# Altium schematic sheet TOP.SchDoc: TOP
size A4; SheetNumber: 1; SheetTotal: 1
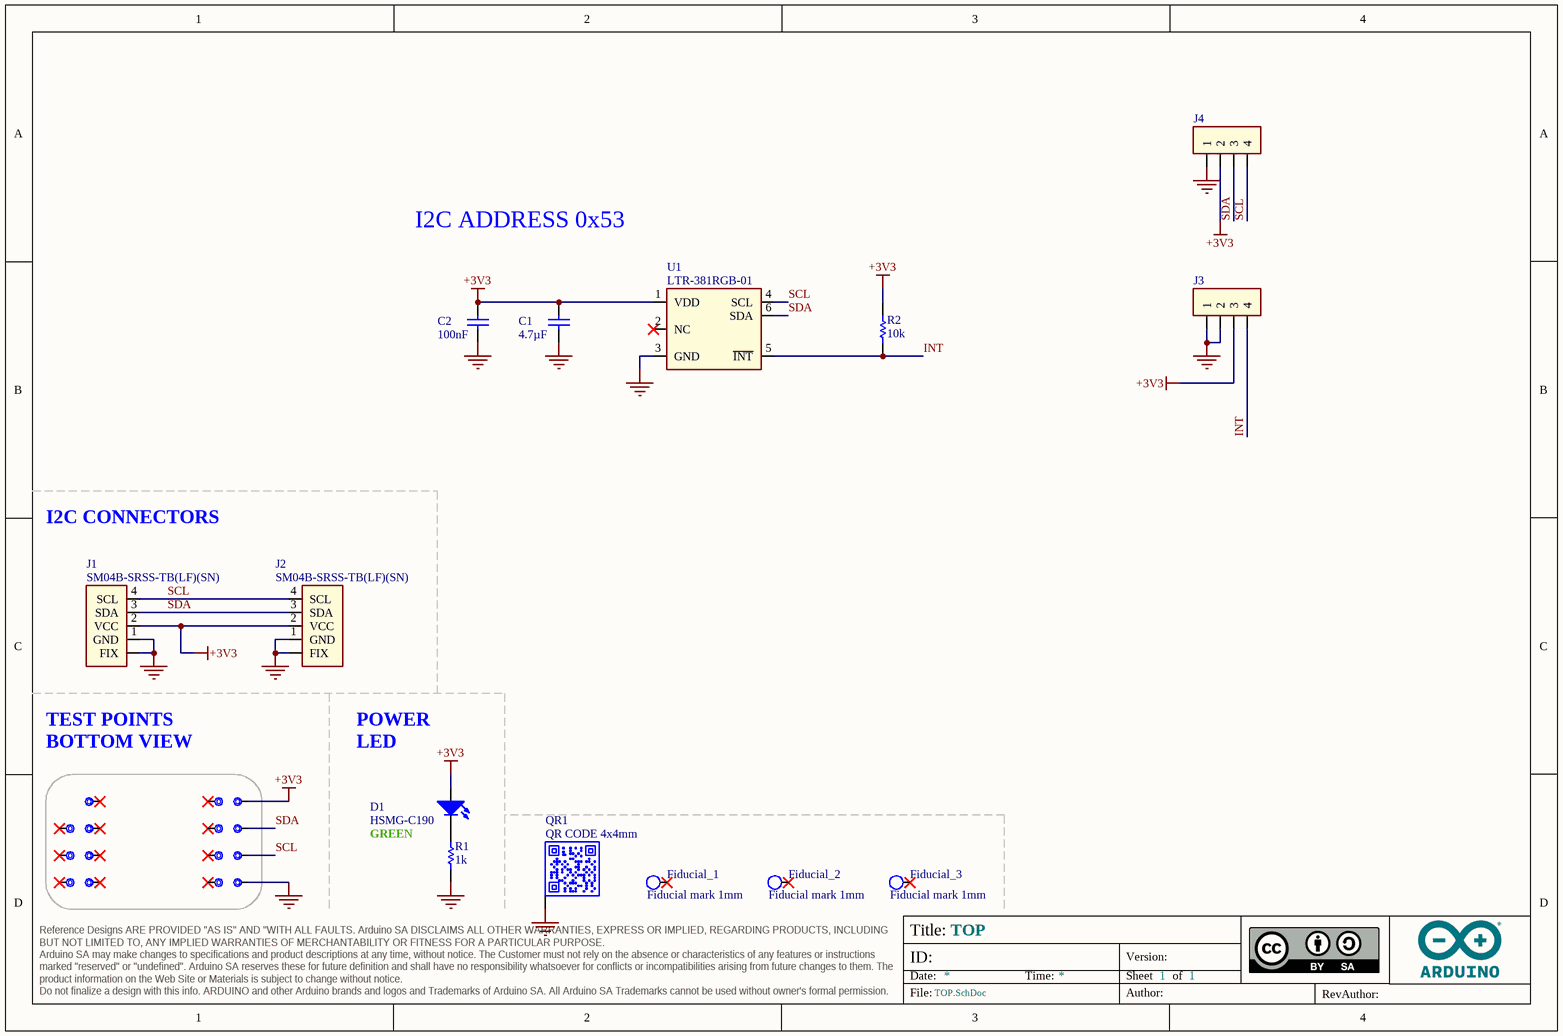
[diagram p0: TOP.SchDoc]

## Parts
3V3  Test point 1.00mm  [TP-1.00MM]  (value not drawn)  (no BOM)
C1  value 4.7µF  [CAP-0603]  (hidden comment: GRM188R61C475KAAJD)
C2  value 100nF  [CAP-0402]  (hidden comment: 0402B104K160CT)
D1  HSMG-C190  [LEDC1608X80N-AK]
Fiducial_1  Fiducial mark 1mm  [Fiducial mark 1mm-Footprint-1]  (no BOM)
Fiducial_2  Fiducial mark 1mm  [Fiducial mark 1mm-Footprint-1]  (no BOM)
Fiducial_3  Fiducial mark 1mm  [Fiducial mark 1mm-Footprint-1]  (no BOM)
GND  Test point 1.00mm  [TP-1.00MM]  (value not drawn)  (no BOM)
J1  SM04B-SRSS-TB(LF)(SN)  [SM04B-SRSS-TB(LF)(SN)-Footprint-1]
J2  SM04B-SRSS-TB(LF)(SN)  [SM04B-SRSS-TB(LF)(SN)-Footprint-1]
J3  HEADER TH 2.54mm VERT. 1x004POS  [PIN HEADER 2.54mm VERT. 1x4POS-Footprint-1]  (value not drawn)  (no BOM)
J4  HEADER TH 2.54mm VERT. 1x004POS  [PIN HEADER 2.54mm VERT. 1x4POS-Footprint-1]  (value not drawn)  (no BOM)
NRST  Test point 1.00mm  [TP-1.00MM]  (value not drawn)  (no BOM)
PA6  Test point 1.00mm  [TP-1.00MM]  (value not drawn)  (no BOM)
PA7  Test point 1.00mm  [TP-1.00MM]  (value not drawn)  (no BOM)
PC14  Test point 1.00mm  [TP-1.00MM]  (value not drawn)  (no BOM)
PC15  Test point 1.00mm  [TP-1.00MM]  (value not drawn)  (no BOM)
QR1  QR CODE 4x4mm  [QR CODE 4x4mm]  (no BOM)
R1  value 1k  [RES-0402]  (hidden comment: CRCW04021K00FKEDC)
R2  value 10k  [RES-0402]  (hidden comment: CRCW040210K0FKED)
SCL  Test point 1.00mm  [TP-1.00MM]  (value not drawn)  (no BOM)
SDA  Test point 1.00mm  [TP-1.00MM]  (value not drawn)  (no BOM)
SWCLK  Test point 1.00mm  [TP-1.00MM]  (value not drawn)  (no BOM)
SWDIO  Test point 1.00mm  [TP-1.00MM]  (value not drawn)  (no BOM)
TP9  Test point 1.00mm  [TP-1.00MM]  (value not drawn)  (no BOM)
TP10  Test point 1.00mm  [TP-1.00MM]  (value not drawn)  (no BOM)
TP11  Test point 1.00mm  [TP-1.00MM]  (value not drawn)  (no BOM)
TP12  Test point 1.00mm  [TP-1.00MM]  (value not drawn)  (no BOM)
U1  LTR-381RGB-01  [SON65P200X70-6N]

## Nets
+3V3: 3V3.X C1.2 C2.1 D1.A J1.2(VCC) J2.2(VCC) J3.3 J4.2 R2.1 U1.1(VDD)
GND: C1.1 C2.2 GND.X J1.1(GND) J1.FIX J2.1(GND) J2.FIX J3.1 J3.2 J4.1 QR1.PAD R1.1 U1.3(GND)
INT: J3.4 R2.2 U1.5(~{INT})
SCL: J1.4(SCL) J2.4(SCL) J4.4 SCL.X U1.4(SCL)
SDA: J1.3(SDA) J2.3(SDA) J4.3 SDA.X U1.6(SDA)
NetD1_C: D1.C R1.2

Not connected (* = marked no-connect by the designer): Fiducial_1 1*; Fiducial_2 1*; Fiducial_3 1*; NRST X*; PA6 X*; PA7 X*; PC14 X*; PC15 X*; SWCLK X*; SWDIO X*; TP9 X*; TP10 X*; TP11 X*; TP12 X*; U1 2(NC)*

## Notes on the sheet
- I2C ADDRESS 0x53
- I2C CONNECTORS
- TEST POINTS BOTTOM VIEW
- (near D1) POWER LED
- GREEN

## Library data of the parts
3V3 GND NRST PA6 PA7 PC14 PC15 SCL SDA SWCLK SWDIO TP9-TP12 = UT0013-A.6: Manufacturer: This is not a component
C1 = C0054-A.16: CAP CHIP 0603 4.7uF 10% 16V X5R; Manufacturer: Murata; Code Arduino: A5072
C2 = C0012-A.15: CAP CHIP 0402 100nF 10% 16V X7R; Manufacturer: Walsin; Code Arduino: 0132
D1 = L0009-A.5: LED SMD 0603 GREEN/568 15mcd 120^; Manufacturer: Broadcom; Code Arduino: 2204
Fiducial_1-Fiducial_3 = UT0023-A.7: Fiducial mark 1mm clearance 2mm
J1 J2 = J0005-A.2: CONN JST 4POS SIDE 1MM TIN QWIIC; Code Arduino: J0005
J3 J4 = J0162-A.6: Code Arduino: J0162
QR1 = QR-0001-A.5: QR CODE 4x4mm on layer 34 (This is not a component); Code Arduino: QRCODE_4x4mm
R1 = R0007-A.24: RES CHIP 0402 1k 1% 1/16W; Manufacturer: Vishay; Code Arduino: 0140; Power: 62.5mW; Temperature coefficient: 100ppm
R2 = R0003-A.24: RES CHIP 0402 10k 1% 1/16W; Manufacturer: Vishay; Code Arduino: 0136; Power: 62.5mW; Temperature coefficient: 100ppm
U1 = U0407-A.3: IC light + RGB sensor , I2C, Vdd 1.7V to 3.6V, DFN 2x2mm; Manufacturer: Liteon; Code Arduino: U0407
